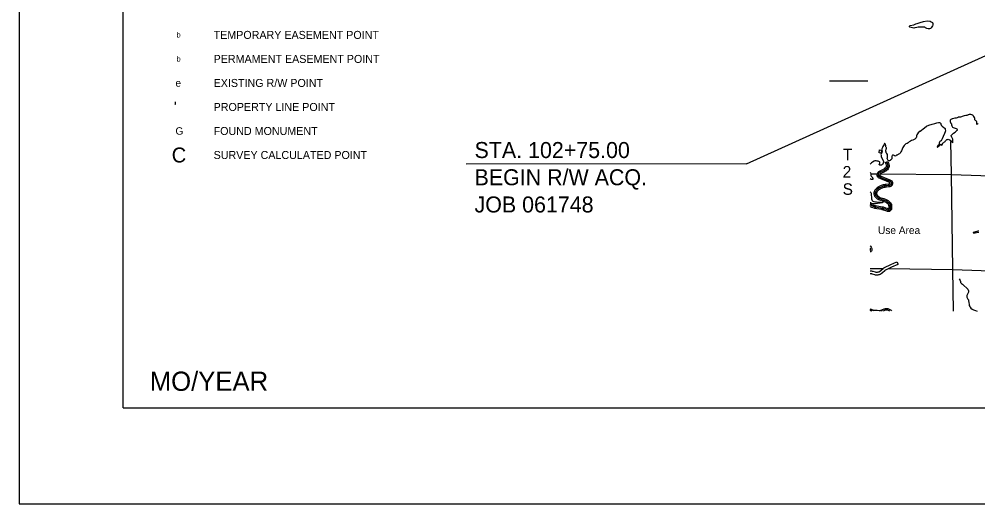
# Model space of a CAD drawing. Extents: x -3711 to 825, y -151 to 1050.
# Drawn here: x -3711 to -3112, y 0 to 303 of the extents above; entities that cross this region are included whole.
import ezdxf

# ---------------------------------------------------------------- set-up
doc = ezdxf.new("R2010")
doc.units = 0
for name, color, linetype in [('Default', 7, 'Continuous'), ('E_Sheet Border', 7, 'Continuous'), ('E_Title Sheet', 7, 'Continuous'), ('Level 31', 7, 'Continuous'), ('Level 32', 7, 'Continuous'), ('Level 35', 7, 'Continuous'), ('Level 46', 7, 'Continuous'), ('Level 5', 7, 'Continuous'), ('Level 57', 7, 'Continuous'), ('Level 7', 7, 'Continuous'), ('Level 9', 7, 'Continuous'), ('R_Dimension', 7, 'Continuous'), ('R_No Plot', 7, 'Continuous')]:
    doc.layers.add(name, color=color, linetype=linetype)

msp = doc.modelspace()

# ---------------------------------------------------------------- linework, layer by layer
at = {"layer": 'E_Sheet Border'}
msp.add_lwpolyline([(-3710.7, 0), (-2060.7, 0), (-2060.7, 1050), (-3710.7, 1050)], close=True, dxfattribs=at)
at = {"layer": 'E_Title Sheet'}
msp.add_line((-3645.7, 60), (-2105.7, 60), dxfattribs=at)
msp.add_lwpolyline([(-3645.7, 60), (-3645.7, 990)], dxfattribs=at)
at = {"layer": 'Level 31'}
for p, q in [((-3169.66, 213.27), (-3168.1, 213.89)), ((-3174.58, 204.5), (-3173.1, 205.29)), ((-3174.58, 204.5), (-3174.58, 204.5)), ((-3167.22, 197.98), (-3167.44, 199.65)), ((-3176.31, 192.31), (-3174.9, 193.22)), ((-3175.59, 186.13), (-3176.07, 184.52)), ((-3165.67, 186.24), (-3167.34, 186.04))]:
    msp.add_line(p, q, dxfattribs=at)
for points in [[(-3168.88, 213.58), (-3168.49, 212.61), (-3168.19, 211.71), (-3168.1, 211.33), (-3168.07, 211.02), (-3168.1, 210.68), (-3168.17, 210.41), (-3168.28, 210.13), (-3168.53, 209.75), (-3168.91, 209.28), (-3169.45, 208.77), (-3169.95, 208.36), (-3170.47, 208.06), (-3172.68, 207.07), (-3172.98, 206.91), (-3173.29, 206.71), (-3173.56, 206.43), (-3173.77, 206.13), (-3173.9, 205.82), (-3173.96, 205.5), (-3173.96, 205.22), (-3173.9, 205.01), (-3173.79, 204.8), (-3173.58, 204.56), (-3173.32, 204.35), (-3173.01, 204.16), (-3172.05, 203.65), (-3170.54, 203.05), (-3167.02, 201.63), (-3166.64, 201.46), (-3166.37, 201.3), (-3166.17, 201.12), (-3166.01, 200.94), (-3165.93, 200.75), (-3165.9, 200.52), (-3165.91, 200.25), (-3165.97, 199.94), (-3166.04, 199.7), (-3166.12, 199.48), (-3166.24, 199.28), (-3166.39, 199.12), (-3166.62, 198.98), (-3166.89, 198.87), (-3167.41, 198.8), (-3168.9, 198.64), (-3169.62, 198.54), (-3170.04, 198.47), (-3170.69, 198.33), (-3171.34, 198.16), (-3171.85, 197.99), (-3172.66, 197.63), (-3173.28, 197.26), (-3174.12, 196.69), (-3174.66, 196.23), (-3174.92, 196.01), (-3175.16, 195.73), (-3175.39, 195.43), (-3175.62, 195.03), (-3175.76, 194.68), (-3175.85, 194.28), (-3175.87, 193.9), (-3175.86, 193.56), (-3175.8, 193.24), (-3175.68, 192.88), (-3175.45, 192.52), (-3175.15, 192.11), (-3174.35, 191.3), (-3173.95, 190.97), (-3173.67, 190.8), (-3173.24, 190.62), (-3171.1, 189.92), (-3170.32, 189.68), (-3169.72, 189.47), (-3169.13, 189.2), (-3168.7, 188.95), (-3168.33, 188.69), (-3167.47, 188), (-3167.01, 187.57), (-3166.85, 187.37), (-3166.7, 187.12), (-3166.63, 186.9), (-3166.56, 186.62), (-3166.5, 186.13), (-3166.48, 185.51), (-3166.49, 184.91), (-3166.53, 184.41), (-3166.6, 184.13), (-3166.76, 183.81), (-3166.99, 183.57), (-3167.26, 183.43), (-3167.52, 183.39), (-3167.76, 183.4), (-3168.05, 183.46), (-3168.4, 183.56), (-3169.53, 183.96), (-3170.47, 184.3), (-3170.85, 184.39), (-3171.38, 184.51), (-3171.66, 184.55), (-3174.82, 185.07), (-3175.68, 185.28)], [(-3169.66, 213.27), (-3169.28, 212.32), (-3168.99, 211.48), (-3168.93, 211.19), (-3168.91, 211.02), (-3168.93, 210.83), (-3168.97, 210.68), (-3169.03, 210.52), (-3169.21, 210.25), (-3169.53, 209.85), (-3170.01, 209.4), (-3170.37, 209.11)], [(-3168.1, 213.89), (-3167.7, 212.9), (-3167.38, 211.94), (-3167.26, 211.46), (-3167.22, 211.02), (-3167.26, 210.53), (-3167.37, 210.14), (-3167.53, 209.74), (-3167.85, 209.26), (-3168.29, 208.7), (-3168.9, 208.13), (-3169.31, 207.8)], [(-3170.37, 209.11), (-3170.43, 209.06), (-3170.85, 208.81), (-3173.05, 207.82), (-3173.41, 207.63), (-3173.83, 207.36), (-3174.21, 206.97), (-3174.51, 206.53), (-3174.71, 206.06), (-3174.8, 205.58), (-3174.8, 205.12), (-3174.7, 204.71), (-3174.58, 204.5)], [(-3168.93, 201.49), (-3170.85, 202.27), (-3172.4, 202.89), (-3173.43, 203.43), (-3173.81, 203.67), (-3174.16, 203.95), (-3174.49, 204.32), (-3174.58, 204.5)], [(-3169.31, 207.8), (-3169.47, 207.67), (-3170.08, 207.31), (-3172.32, 206.31), (-3172.55, 206.19), (-3172.75, 206.05), (-3172.91, 205.89), (-3173.02, 205.73), (-3173.09, 205.58), (-3173.12, 205.42), (-3173.12, 205.33), (-3173.11, 205.31), (-3173.1, 205.29)], [(-3173.1, 205.29), (-3173.1, 205.29), (-3173, 205.17), (-3172.83, 205.04), (-3172.59, 204.89), (-3171.7, 204.42), (-3170.23, 203.83), (-3168.29, 203.05)], [(-3173.46, 198.13), (-3173.73, 197.97), (-3174.63, 197.36), (-3175.2, 196.87), (-3175.51, 196.61), (-3175.81, 196.26), (-3176.09, 195.9), (-3176.38, 195.4), (-3176.57, 194.93), (-3176.68, 194.4), (-3176.71, 193.91), (-3176.7, 193.48), (-3176.62, 193.03), (-3176.44, 192.51), (-3176.31, 192.31)], [(-3167.44, 199.65), (-3167.51, 199.64), (-3169, 199.48), (-3169.75, 199.37), (-3170.19, 199.29), (-3170.88, 199.15), (-3171.58, 198.97), (-3172.16, 198.77), (-3173.05, 198.38), (-3173.46, 198.13)], [(-3167.22, 197.98), (-3167.31, 197.97), (-3168.79, 197.81), (-3169.49, 197.71), (-3169.88, 197.64), (-3170.5, 197.51), (-3171.09, 197.36), (-3171.54, 197.2), (-3172.27, 196.88), (-3172.59, 196.69)], [(-3167.44, 199.65), (-3167.1, 199.69), (-3166.99, 199.73), (-3166.93, 199.77), (-3166.92, 199.79), (-3166.89, 199.84), (-3166.84, 199.97), (-3166.79, 200.14), (-3166.75, 200.34), (-3166.74, 200.48), (-3166.75, 200.51), (-3166.77, 200.53), (-3166.86, 200.61), (-3167.03, 200.71), (-3167.35, 200.85), (-3168.93, 201.49)], [(-3168.29, 203.05), (-3166.69, 202.4), (-3166.26, 202.21), (-3165.87, 201.98), (-3165.57, 201.71), (-3165.29, 201.39), (-3165.11, 200.97), (-3165.06, 200.56), (-3165.07, 200.16), (-3165.15, 199.74), (-3165.24, 199.43), (-3165.36, 199.12), (-3165.56, 198.78), (-3165.85, 198.47), (-3166.24, 198.22), (-3166.69, 198.05), (-3167.22, 197.98)], [(-3170.95, 188.99), (-3171.35, 189.11), (-3173.54, 189.83), (-3174.05, 190.05), (-3174.43, 190.28), (-3174.92, 190.67), (-3175.79, 191.56), (-3176.14, 192.04), (-3176.31, 192.31)], [(-3172.59, 196.69), (-3172.83, 196.55), (-3173.61, 196.02), (-3174.12, 195.59), (-3174.33, 195.41), (-3174.51, 195.2), (-3174.69, 194.96), (-3174.86, 194.66), (-3174.96, 194.44), (-3175.01, 194.17), (-3175.03, 193.89), (-3175.02, 193.65), (-3174.99, 193.45), (-3174.92, 193.25), (-3174.9, 193.22)], [(-3174.9, 193.22), (-3174.75, 192.99), (-3174.51, 192.65), (-3173.78, 191.92), (-3173.46, 191.66), (-3173.29, 191.55), (-3172.94, 191.41), (-3170.84, 190.72), (-3170.46, 190.6)], [(-3179.03, 187.67), (-3178.5, 187.25), (-3178.11, 187.01), (-3177.4, 186.7), (-3176.13, 186.29), (-3175.59, 186.13)], [(-3175.68, 185.28), (-3176.38, 185.48), (-3177.7, 185.92), (-3178.5, 186.27), (-3178.97, 186.56), (-3179.03, 186.61)], [(-3169.76, 184.93), (-3170.22, 185.1), (-3170.65, 185.21), (-3171.23, 185.33), (-3171.53, 185.38), (-3174.66, 185.9), (-3175.46, 186.09), (-3175.59, 186.13)], [(-3167.34, 186.04), (-3167.39, 186.47), (-3167.44, 186.66), (-3167.47, 186.77), (-3167.54, 186.9), (-3167.62, 186.99), (-3168.02, 187.36), (-3168.83, 188.01), (-3169.16, 188.24), (-3169.52, 188.46), (-3170.03, 188.69), (-3170.58, 188.88), (-3170.95, 188.99)], [(-3170.46, 190.6), (-3170.05, 190.48), (-3169.4, 190.25), (-3168.74, 189.95), (-3168.24, 189.66), (-3167.82, 189.36), (-3166.92, 188.64), (-3166.39, 188.14), (-3166.15, 187.85), (-3165.94, 187.46), (-3165.82, 187.13), (-3165.73, 186.77), (-3165.67, 186.24)], [(-3165.67, 186.24), (-3165.66, 186.2), (-3165.63, 185.52), (-3165.65, 184.86), (-3165.7, 184.27), (-3165.81, 183.84), (-3166.06, 183.32), (-3166.48, 182.89), (-3166.99, 182.62), (-3167.48, 182.54), (-3167.86, 182.57), (-3168.25, 182.64), (-3168.66, 182.75), (-3169.82, 183.17), (-3170.32, 183.35)], [(-3167.34, 186.06), (-3167.32, 185.5), (-3167.33, 184.95), (-3167.36, 184.55), (-3167.39, 184.42), (-3167.45, 184.3), (-3167.5, 184.25), (-3167.53, 184.24), (-3167.57, 184.23), (-3167.66, 184.24), (-3167.86, 184.28), (-3168.15, 184.36), (-3169.25, 184.75), (-3169.76, 184.93)], [(-3176.07, 184.52), (-3176.63, 184.68), (-3178, 185.13), (-3178.89, 185.52), (-3179.03, 185.61)], [(-3170.32, 183.35), (-3170.72, 183.49), (-3171.04, 183.58), (-3171.53, 183.68), (-3171.8, 183.72), (-3174.99, 184.25), (-3175.9, 184.47), (-3176.07, 184.52)], [(-3179.03, 161.22), (-3178.79, 160.91), (-3178.38, 160.29), (-3178.14, 159.84), (-3178.02, 159.42), (-3177.98, 159.05), (-3177.98, 158.76), (-3178.01, 158.5), (-3178.05, 158.21), (-3178.26, 157.73), (-3178.74, 157.36), (-3179.03, 157.26)], [(-3178.82, 159.01), (-3178.85, 159.26), (-3178.92, 159.52), (-3179.03, 159.73)], [(-3179.03, 158.2), (-3178.95, 158.27), (-3178.87, 158.44), (-3178.85, 158.61), (-3178.82, 158.81), (-3178.82, 159.01)]]:
    msp.add_lwpolyline(points, dxfattribs=at)
at = {"layer": 'Level 32'}
for p, q in [((-3177.15, 120.92), (-3177.32, 120.35)), ((-3171.88, 120.87), (-3171.66, 120.35)), ((-3165.66, 120.84), (-3165.87, 120.35))]:
    msp.add_line(p, q, dxfattribs=at)
for points in [[(-3177.12, 120.91), (-3177.4, 121.02), (-3177.8, 121.21), (-3178.16, 121.35), (-3178.59, 121.43), (-3178.97, 121.49), (-3179.03, 121.5)], [(-3177.96, 120.35), (-3178.13, 120.44), (-3178.4, 120.54), (-3178.73, 120.61), (-3179.03, 120.65)], [(-3171.88, 120.87), (-3171.97, 120.84), (-3172.52, 120.66), (-3172.66, 120.62), (-3172.7, 120.62), (-3172.96, 120.62), (-3173.47, 120.62), (-3174.73, 120.65), (-3175.96, 120.73), (-3176.47, 120.77), (-3176.71, 120.79), (-3176.9, 120.84), (-3177.15, 120.92)], [(-3165.66, 120.84), (-3167.78, 121.74), (-3168.12, 121.79), (-3168.44, 121.83), (-3169, 121.85), (-3169.29, 121.83), (-3169.52, 121.79), (-3169.74, 121.74), (-3170.04, 121.65), (-3170.44, 121.48), (-3171.88, 120.87)], [(-3166.67, 120.35), (-3168.02, 120.93), (-3168.23, 120.96), (-3168.5, 120.99), (-3168.98, 121.01), (-3169.18, 120.99), (-3169.37, 120.96), (-3169.53, 120.93), (-3169.75, 120.86), (-3170.11, 120.71), (-3170.95, 120.35)]]:
    msp.add_lwpolyline(points, dxfattribs=at)
at = {"layer": 'Level 35'}
for points in [[(-3123.52, 140.46), (-3122.9, 139.38), (-3122.69, 138.83), (-3122.53, 138.27), (-3122.31, 137.9), (-3122.01, 137.62), (-3121.45, 137.13), (-3120.49, 136.3), (-3118.7, 134.66), (-3118.12, 134.04), (-3117.78, 133.49), (-3117.69, 133.21), (-3117.62, 132.87), (-3117.62, 132.56), (-3117.72, 132.19), (-3117.87, 131.82), (-3118.24, 130.98), (-3118.46, 130.55), (-3118.67, 130.06), (-3118.74, 129.66), (-3118.7, 129.16), (-3118.49, 128.67), (-3117.96, 127.86), (-3117.71, 127.33), (-3117.56, 126.77), (-3117.46, 125.84), (-3117.3, 124.48), (-3117.12, 123.81)], [(-3117.12, 123.81), (-3116.89, 123.27), (-3116.59, 122.77), (-3116.17, 122.3), (-3115.43, 121.62), (-3114.59, 121.15), (-3113.33, 120.69), (-3112.17, 120.35)]]:
    msp.add_lwpolyline(points, dxfattribs=at)
at = {"layer": 'Level 46'}
for points in [[(-3179.03, 145.49), (-3178.83, 145.48), (-3178.4, 145.46), (-3178.15, 145.44), (-3177.89, 145.41), (-3177.64, 145.37), (-3177.41, 145.32), (-3175.9, 144.84), (-3175.61, 144.76), (-3175.42, 144.72), (-3175.2, 144.69), (-3174.95, 144.68), (-3174.66, 144.69), (-3174.55, 144.7), (-3174.41, 144.72), (-3174.13, 144.79), (-3173.78, 144.89), (-3173.5, 144.98), (-3173.41, 145.02), (-3173.32, 145.07), (-3173.15, 145.2), (-3172.42, 145.77), (-3170.97, 147.02), (-3170.62, 147.32), (-3170.39, 147.48), (-3170.15, 147.62), (-3166.21, 149.57), (-3162.3, 151.19), (-3161.65, 149.64)], [(-3179.03, 143.81), (-3178.91, 143.8), (-3178.5, 143.78), (-3178.31, 143.77), (-3178.12, 143.75), (-3177.97, 143.72), (-3177.86, 143.7), (-3176.38, 143.23), (-3176, 143.12), (-3175.71, 143.06), (-3175.34, 143.01), (-3174.95, 143), (-3174.54, 143.01), (-3174.31, 143.03), (-3174.08, 143.07), (-3173.71, 143.16), (-3173.29, 143.28), (-3172.89, 143.41), (-3172.62, 143.53), (-3172.4, 143.67), (-3172.14, 143.85), (-3171.35, 144.48), (-3169.88, 145.74), (-3169.6, 145.98), (-3169.49, 146.05), (-3169.35, 146.14), (-3165.52, 148.03), (-3161.65, 149.64)]]:
    msp.add_lwpolyline(points, dxfattribs=at)
at = {"layer": 'Level 5'}
for points in [[(-3127.08, 120.35), (-3127.4, 146.29), (-3128.3, 205.73), (-3128.63, 226.29)], [(-3178.63, 206.14), (-3174.69, 206.11)], [(-3172.62, 206.09), (-3128.3, 205.73), (-3073.19, 203.84)], [(-3179.03, 147.05), (-3171.21, 146.94)], [(-3167.62, 146.88), (-3127.4, 146.29), (-3068.28, 144.32), (-3045.31, 143.87)]]:
    msp.add_lwpolyline(points, dxfattribs=at)
at = {"layer": 'Level 57'}
msp.add_lwpolyline([(-3171.76, 219.01), (-3173.45, 219.31), (-3173.15, 220.99), (-3171.46, 220.7)], close=True, dxfattribs=at)
at = {"layer": 'Level 9'}
for points in [[(-3145.65, 301.33), (-3143.42, 301.61), (-3141.6, 301.38), (-3141.03, 300.97), (-3140.52, 300.78), (-3140.22, 300.59), (-3139.88, 299.97), (-3140, 298.95), (-3140.17, 298.45), (-3141.01, 297.26), (-3141.44, 296.93), (-3142.02, 296.68), (-3142.88, 296.72), (-3143.58, 296.95), (-3144.44, 297.32), (-3144.97, 297.62), (-3145.61, 297.77), (-3146.86, 297.69), (-3149.06, 297.76), (-3149.82, 297.59), (-3151.08, 297.22), (-3151.75, 297.15), (-3152.69, 297.23), (-3154.37, 297.73), (-3154.52, 297.97), (-3154.41, 298.32), (-3154, 298.64), (-3151.87, 299.25), (-3150.44, 299.8), (-3149.65, 300.01), (-3147.16, 300.89), (-3146.26, 301.05), (-3145.65, 301.33)], [(-3128.04, 236.61), (-3128.04, 236.85), (-3128.11, 237.07), (-3128.29, 237.35), (-3128.53, 237.6), (-3128.68, 237.78), (-3128.71, 238.06), (-3128.78, 238.42), (-3128.89, 238.63), (-3128.96, 238.88), (-3128.96, 239.27), (-3128.96, 239.55), (-3128.89, 239.9), (-3128.71, 240.15), (-3128.53, 240.3), (-3128.14, 240.51), (-3127.72, 240.65), (-3127.36, 240.72), (-3125.88, 241.04), (-3125.2, 241.11), (-3124.53, 241.18), (-3124.17, 241.39), (-3123.78, 241.61), (-3123.64, 241.64), (-3123.22, 241.64), (-3122.79, 241.75), (-3122.51, 241.78), (-3121.87, 241.86), (-3121.41, 242.1), (-3120.06, 242.53), (-3119.32, 242.81), (-3118.93, 242.81), (-3118.54, 242.81), (-3118.11, 242.88), (-3117.69, 243.1), (-3117.41, 243.24), (-3116.91, 243.31), (-3116.48, 243.31), (-3115.81, 243.24), (-3115.39, 243.03), (-3115.1, 242.85), (-3114.71, 242.53), (-3114.43, 241.82), (-3114.04, 241.36), (-3113.97, 241.08), (-3113.97, 240.61), (-3113.97, 240.33), (-3113.93, 240.05), (-3113.72, 239.73), (-3113.51, 239.66), (-3113.12, 239.48), (-3112.83, 239.16), (-3112.62, 238.66), (-3112.59, 238.1), (-3112.59, 237.74), (-3112.59, 237.35), (-3112.55, 237.24), (-3112.37, 237.21), (-3112.09, 237.28), (-3111.88, 237.42), (-3111.63, 237.6)], [(-3147.88, 232.69), (-3145.15, 234.89), (-3143.77, 235.81), (-3142.39, 236.49), (-3140.41, 237.16), (-3138.63, 237.55), (-3137.46, 237.9), (-3136.44, 238.12), (-3135.8, 238.19), (-3135.23, 237.98), (-3134.98, 237.62), (-3134.81, 237.09), (-3134.66, 236.56), (-3134.1, 235.88), (-3133.03, 235.03), (-3132.5, 234.68), (-3132.18, 234.32), (-3132.11, 233.76), (-3132.08, 232.97), (-3132.25, 232.3), (-3132.72, 231.24), (-3133.53, 229.43), (-3134.13, 227.87), (-3134.7, 226.8), (-3135.09, 226.56), (-3135.37, 226.45), (-3135.55, 226.31), (-3135.87, 225.53), (-3135.9, 225.1), (-3135.8, 224.75), (-3135.8, 224.53), (-3135.94, 224.32), (-3136.22, 224.21), (-3136.61, 224.04), (-3136.83, 223.82), (-3137, 223.36), (-3137.14, 222.9), (-3137.25, 222.65), (-3137.04, 222.76), (-3136.51, 223.19), (-3135.87, 223.58), (-3135.44, 223.9), (-3135.09, 224.18), (-3134.91, 224.39), (-3134.7, 224.43), (-3134.59, 224.29), (-3134.56, 224.11), (-3134.45, 223.97), (-3134.31, 223.93), (-3134.2, 223.93), (-3134.03, 224.18), (-3134.03, 224.32), (-3133.92, 224.68), (-3133.85, 224.96), (-3133.74, 225.21), (-3133.49, 225.49), (-3133.14, 225.74), (-3132.72, 226.02), (-3132.25, 226.34), (-3131.97, 226.66), (-3131.76, 227.02), (-3131.44, 227.41), (-3131.12, 227.55), (-3130.77, 227.62), (-3130.34, 227.66), (-3129.88, 227.62), (-3129.35, 227.34), (-3128.5, 226.63), (-3128.18, 226.27), (-3127.86, 225.95), (-3127.61, 225.67), (-3127.47, 225.49), (-3127.4, 225.56), (-3127.36, 225.95), (-3127.36, 226.38), (-3127.36, 227.05), (-3127.43, 227.76), (-3127.61, 228.26), (-3127.9, 228.68), (-3128.14, 228.97), (-3128.25, 229.32), (-3128.36, 229.68), (-3128.36, 230.07), (-3128.25, 230.31), (-3127.61, 230.95), (-3126.9, 231.52), (-3126.05, 232.09), (-3125.41, 232.73), (-3124.99, 233.26), (-3124.74, 233.33), (-3124.56, 233.44), (-3124.53, 233.68), (-3124.64, 233.9), (-3125.1, 234.22), (-3125.77, 234.46), (-3126.41, 234.71), (-3127.01, 234.82), (-3127.33, 235.1), (-3127.9, 235.9), (-3128.04, 236.39), (-3128.04, 236.61)], [(-3147.88, 232.69), (-3149.02, 231.69), (-3149.92, 230.44), (-3150.13, 229.96), (-3150.16, 229.3), (-3150.28, 228.68), (-3150.46, 228.32), (-3151.11, 227.75), (-3152.46, 227.03), (-3153.2, 226.92), (-3153.95, 226.53), (-3154.75, 225.99), (-3155.41, 225.39), (-3155.98, 225), (-3156.72, 224.82), (-3157.44, 224.26), (-3157.89, 223.75), (-3158.57, 222.52), (-3159.53, 220.55), (-3159.83, 219.75), (-3160.13, 219.36), (-3160.37, 218.94), (-3160.81, 218.61), (-3161.41, 218.43), (-3161.65, 218.25), (-3161.89, 217.93), (-3162.1, 217.81), (-3162.66, 217.69), (-3162.87, 217.42), (-3163.05, 217.24), (-3163.44, 217.18), (-3163.71, 217.24), (-3164.1, 217.45), (-3164.45, 217.72), (-3164.75, 217.84), (-3164.9, 217.84), (-3165.11, 217.72), (-3165.38, 217.39), (-3165.47, 217.03), (-3165.62, 215.92), (-3165.62, 215.51), (-3165.71, 215.24), (-3165.98, 215.06), (-3166.33, 214.88), (-3166.42, 214.67), (-3166.57, 214.4), (-3166.93, 214.25), (-3167.38, 214.22), (-3167.8, 214.43), (-3168.04, 214.76), (-3168.33, 215.18), (-3168.39, 215.8), (-3168.33, 216.31), (-3168.21, 217.51), (-3168.33, 218.22), (-3168.6, 218.73), (-3168.99, 219.15)], [(-3168.99, 219.15), (-3169.11, 219.66), (-3169.23, 220.17), (-3169.26, 220.49), (-3169.26, 220.91), (-3169.14, 221.33), (-3168.99, 221.69), (-3168.93, 221.96), (-3168.93, 222.26), (-3168.99, 222.55), (-3169.17, 222.97), (-3169.29, 223.24), (-3169.35, 223.69), (-3169.53, 224.29), (-3169.68, 224.91), (-3169.8, 225), (-3170.01, 224.94), (-3170.24, 224.41), (-3170.69, 223.81), (-3171.08, 223.15), (-3171.44, 222.58), (-3171.74, 221.75), (-3172.03, 220.55), (-3172.24, 219.42), (-3172.27, 218.82), (-3172.33, 218.13), (-3172.27, 217.66), (-3172.18, 216.85), (-3171.8, 215.95), (-3170.93, 214.4), (-3170.66, 213.71), (-3170.66, 213.31), (-3170.84, 212.74), (-3171.17, 212.2), (-3171.5, 211.87), (-3171.77, 211.61), (-3172.18, 211.49), (-3172.72, 211.49), (-3173.08, 211.55), (-3173.29, 211.67), (-3173.35, 211.75), (-3173.35, 212.02), (-3173.26, 212.38), (-3173.05, 212.86), (-3173.05, 213.1), (-3173.08, 213.43), (-3173.23, 213.61), (-3173.71, 213.79), (-3174.09, 213.93), (-3174.6, 214.05), (-3175.29, 214.23), (-3175.79, 214.26), (-3176.21, 214.23), (-3176.57, 214.02), (-3177.53, 213.37), (-3178.18, 212.98), (-3178.51, 212.77), (-3178.75, 212.44), (-3179.02, 212.17), (-3179.03, 212.16)], [(-3179.03, 207.07), (-3178.78, 206.74), (-3178.66, 206.23), (-3178.72, 205.75), (-3178.72, 205.39), (-3178.54, 204.97), (-3178.33, 204.59), (-3178.06, 204.2), (-3177.68, 203.78), (-3177.53, 203.6), (-3177.35, 203.3), (-3177.32, 202.97), (-3177.32, 202.79), (-3177.38, 202.56), (-3177.59, 202.47), (-3178.03, 202.47), (-3178.51, 202.65), (-3179.03, 203.02)], [(-3179.03, 194.85), (-3178.69, 194.4), (-3178.51, 193.95), (-3178.39, 193.27), (-3178.3, 191.21), (-3178.21, 190.52), (-3178.12, 189.89), (-3177.82, 189.35), (-3177.38, 188.94), (-3176.75, 188.73), (-3175.74, 188.52), (-3175.2, 188.52), (-3174.12, 188.46), (-3173.29, 188.43), (-3172.63, 188.34), (-3171.94, 188.25), (-3171.44, 188.22), (-3170.9, 188.43), (-3171.71, 188.04), (-3172.87, 187.77), (-3174.45, 187.47), (-3175.82, 187.26), (-3177.08, 187.26), (-3178.15, 187.47), (-3178.93, 187.89), (-3179.03, 188.02)], [(-3111.29, 170.64), (-3111.89, 170.36), (-3112.52, 170.14), (-3113.28, 169.94), (-3113.84, 169.73), (-3114.43, 169.49), (-3114.72, 169.38), (-3114.7, 169.18), (-3114.28, 169.18), (-3113.37, 169.33), (-3112.65, 169.47), (-3111.88, 169.64), (-3111.14, 169.75)]]:
    msp.add_lwpolyline(points, dxfattribs=at)
at = {"layer": 'R_Dimension'}
for p, q in [((-3256.28, 212.32), (-2869.43, 387.55)), ((-3204.54, 264.18), (-3180.54, 264.17))]:
    msp.add_line(p, q, dxfattribs=at)
msp.add_lwpolyline([(-3256.28, 212.32), (-3431.45, 212.19)], dxfattribs=at)
at = {"layer": 'R_No Plot'}
msp.add_lwpolyline([(-3710.7, 0), (-2060.7, 0), (-2060.7, 1050), (-3710.7, 1050)], close=True, dxfattribs=at)

# ---------------------------------------------------------------- texts
at = {"layer": 'Default'}
for s, p in [('T', (-3196.1, 214.58)), ('2', (-3196.23, 203.78)), ('S', (-3196.25, 192.98))]:
    msp.add_text(s, height=7.2, dxfattribs=at).set_placement(p)
at = {"layer": 'E_Title Sheet'}
for s, height, p in [('b', 3.28, (-3612.35, 291.22)), ('TEMPORARY EASEMENT POINT', 5, (-3589.22, 290.36)), ('b', 3.28, (-3612.35, 276.22)), ('PERMAMENT EASEMENT POINT', 5, (-3589.22, 275.36)), ('e', 4.68, (-3613.06, 260.52)), ('EXISTING R/W POINT', 5, (-3589.22, 260.36)), ("'", 6.55, (-3613.99, 244.59)), ('PROPERTY LINE POINT', 5, (-3589.22, 245.36)), ('G', 4.68, (-3613.06, 230.52)), ('FOUND MONUMENT', 5, (-3589.22, 230.36)), ('C', 9.36, (-3615.4, 213.18)), ('SURVEY CALCULATED POINT', 5, (-3589.22, 215.36)), ('MO/YEAR', 12, (-3629.13, 70.57))]:
    msp.add_text(s, height=height, dxfattribs=at).set_placement(p)
at = {"layer": 'Level 7'}
msp.add_text('Use Area', height=4.734, dxfattribs=at).set_placement((-3174.18, 168.5))
at = {"layer": 'R_Dimension'}
for s, p in [('STA. 102+75.00', (-3426.21, 215.96)), ('BEGIN R/W ACQ.', (-3426.21, 198.96)), ('JOB 061748', (-3426.21, 181.96))]:
    msp.add_text(s, height=10, rotation=359.9994, dxfattribs=at).set_placement(p)

doc.saveas('drawing.dxf')
